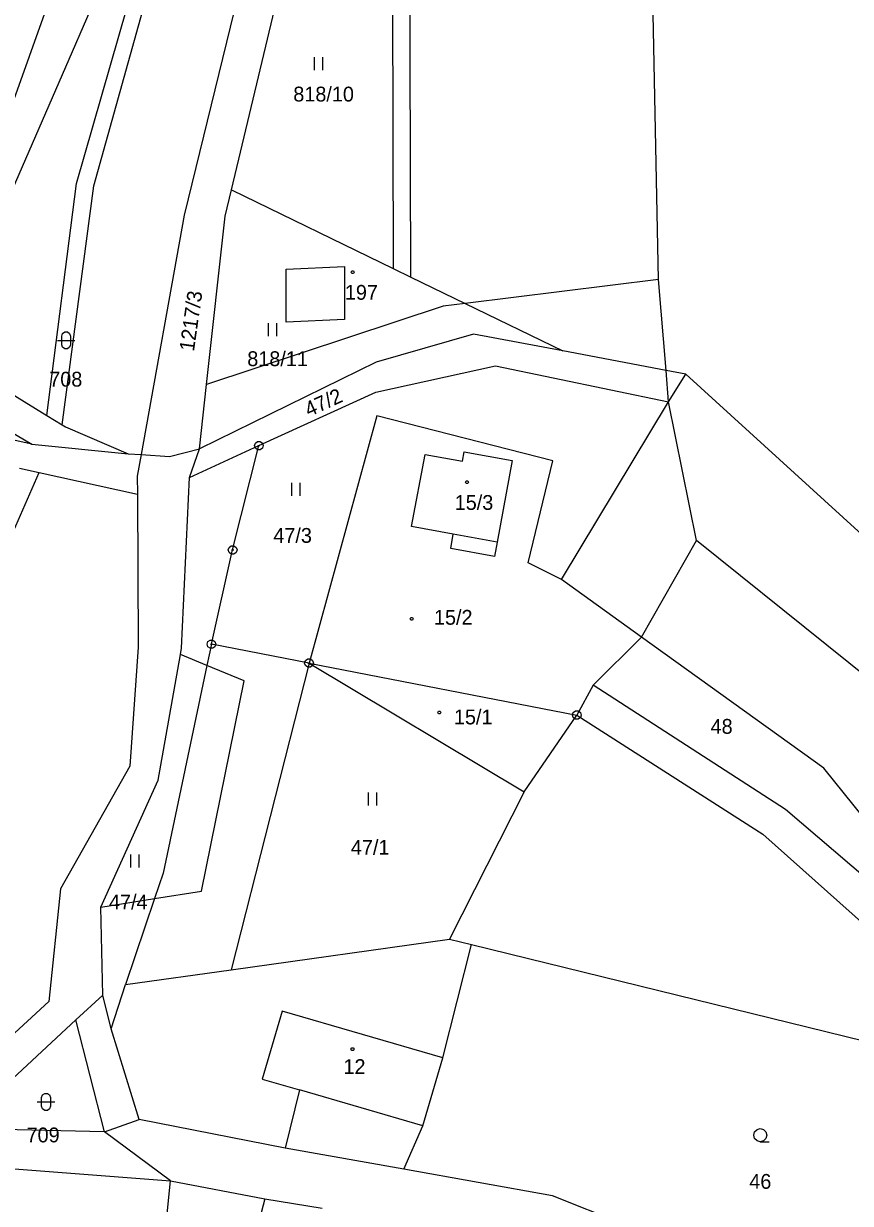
# Model space of a CAD drawing. Extents: x -694465 to -690527, y -983694 to -978978.
# Drawn here: x -691741.4 to -691646.5, y -980787.1 to -980651.8 of the extents above; entities that cross this region are included whole.
import ezdxf

# ---------------------------------------------------------------- set-up
doc = ezdxf.new("R2010")
doc.units = 0
for name, color, linetype in [('Vrstva 1', 7, 'Continuous'), ('Vrstva 18', 7, 'Continuous'), ('Vrstva 19', 7, 'Continuous'), ('Vrstva 24', 7, 'Continuous'), ('Vrstva 25', 7, 'Continuous')]:
    doc.layers.add(name, color=color, linetype=linetype)

msp = doc.modelspace()

# ---------------------------------------------------------------- linework, layer by layer
at = {"layer": 'Vrstva 1'}
for points in [[(-691668.525, -980681.164), (-691670.964, -980559.282)], [(-691736.928, -980697.827), (-691733.29, -980670.39), (-691727.725, -980650.392), (-691718.608, -980627.912), (-691709.081, -980604.134)], [(-691738.701, -980696.735), (-691735.302, -980670.152), (-691729.5, -980649.92), (-691711.265, -980604.887)], [(-691719.6, -980617.78), (-691750.73, -980689.325)], [(-691709.28, -980617.94), (-691722.95, -980673.77)], [(-691699.12, -980617.79), (-691698.96, -980679.9)], [(-691696.95, -980680.87), (-691697.12, -980616.78)], [(-691717.51, -980670.88), (-691709.24, -980636.26)], [(-691738.19, -980648.47), (-691745.62, -980669.17)], [(-691718.23, -980673.88), (-691717.51, -980670.88)], [(-691717.51, -980670.88), (-691698.96, -980679.9)], [(-691722.95, -980673.77), (-691727.877, -980701.231)], [(-691720.376, -980693.171), (-691718.23, -980673.88)], [(-691704.543, -980679.637), (-691704.543, -980685.745), (-691711.258, -980686.05), (-691711.258, -980679.942), (-691704.543, -980679.637)], [(-691698.96, -980679.9), (-691696.95, -980680.87)], [(-691696.95, -980680.87), (-691690.707, -980683.904)], [(-691668.525, -980681.164), (-691690.707, -980683.904)], [(-691667.667, -980691.573), (-691668.525, -980681.164)], [(-691690.707, -980683.904), (-691693.249, -980684.218), (-691720.376, -980693.171)], [(-691690.707, -980683.904), (-691679.52, -980689.34)], [(-691689.74, -980687.42), (-691700.91, -980690.62)], [(-691679.52, -980689.34), (-691689.74, -980687.42)], [(-691750.73, -980689.325), (-691738.701, -980696.735)], [(-691667.667, -980691.573), (-691679.52, -980689.34)], [(-691700.91, -980690.62), (-691721.2, -980700.58)], [(-691700.96, -980694.05), (-691687.23, -980691.05)], [(-691687.23, -980691.05), (-691667.37, -980695.17)], [(-691665.4, -980692), (-691667.667, -980691.573)], [(-691667.37, -980695.17), (-691667.667, -980691.573)], [(-691667.37, -980695.17), (-691665.4, -980692)], [(-691665.4, -980692), (-691620.71, -980732.71)], [(-691751.454, -980693.536), (-691740.424, -980700.027)], [(-691721.2, -980700.58), (-691720.376, -980693.171)], [(-691714.37, -980700.2), (-691700.96, -980694.05)], [(-691679.67, -980715.55), (-691667.37, -980695.17)], [(-691664.189, -980711.076), (-691667.37, -980695.17)], [(-691738.701, -980696.735), (-691736.928, -980697.827)], [(-691700.84, -980696.77), (-691708.62, -980725.14)], [(-691680.67, -980701.94), (-691700.84, -980696.77)], [(-691740.424, -980700.027), (-691744.629, -980699.131)], [(-691736.928, -980697.827), (-691736.557, -980698.055), (-691729.375, -980701.131)], [(-691740.424, -980700.027), (-691729.375, -980701.131)], [(-691722.32, -980703.84), (-691714.37, -980700.2)], [(-691717.38, -980712.16), (-691714.37, -980700.2)], [(-691729.375, -980701.131), (-691727.877, -980701.231)], [(-691727.877, -980701.231), (-691728.32, -980703.7)], [(-691727.877, -980701.231), (-691724.639, -980701.446), (-691721.2, -980700.58)], [(-691722.32, -980703.84), (-691721.2, -980700.58)], [(-691692.07, -980710.35), (-691696.86, -980709.48), (-691695.31, -980701.2), (-691691.01, -980701.98), (-691690.82, -980700.9), (-691685.33, -980701.9)], [(-691741.821, -980702.772), (-691739.583, -980703.266)], [(-691685.33, -980701.9), (-691687.04, -980711.26)], [(-691683.48, -980713.66), (-691680.67, -980701.94)], [(-691752.177, -980776.563), (-691745.117, -980741.052), (-691744.643, -980721.651), (-691743.341, -980711.832), (-691739.583, -980703.266)], [(-691739.583, -980703.266), (-691728.309, -980705.76)], [(-691728.32, -980703.7), (-691728.309, -980705.76)], [(-691723.25, -980723.43), (-691722.32, -980703.84)], [(-691728.309, -980705.76), (-691728.22, -980723.31)], [(-691687.04, -980711.26), (-691687.33, -980712.9), (-691692.37, -980711.98), (-691692.07, -980710.35)], [(-691687.04, -980711.26), (-691692.07, -980710.35)], [(-691670.47, -980722.16), (-691664.189, -980711.076)], [(-691623.724, -980758.29), (-691619.32, -980747.113), (-691664.189, -980711.076)], [(-691719.81, -980722.97), (-691717.38, -980712.16)], [(-691679.67, -980715.55), (-691683.48, -980713.66)], [(-691670.47, -980722.16), (-691679.67, -980715.55)], [(-691728.22, -980723.31), (-691729.17, -980736.97)], [(-691723.376, -980724.139), (-691723.25, -980723.43)], [(-691719.81, -980722.97), (-691720.324, -980725.403)], [(-691708.62, -980725.14), (-691719.81, -980722.97)], [(-691670.47, -980722.16), (-691676.01, -980727.68)], [(-691649.58, -980737.18), (-691670.47, -980722.16)], [(-691725.93, -980738.57), (-691723.376, -980724.139)], [(-691720.324, -980725.403), (-691723.376, -980724.139)], [(-691726.347, -980752.158), (-691720.942, -980751.296), (-691716.058, -980727.169), (-691720.324, -980725.403)], [(-691720.324, -980725.403), (-691725.36, -980749.24)], [(-691708.62, -980725.14), (-691717.552, -980760.31)], [(-691708.62, -980725.14), (-691683.95, -980739.89)], [(-691708.62, -980725.14), (-691677.9, -980731.1)], [(-691676.01, -980727.68), (-691677.9, -980731.1)], [(-691653.97, -980741.92), (-691676.01, -980727.68)], [(-691683.95, -980739.89), (-691677.9, -980731.1)], [(-691677.9, -980731.1), (-691656.57, -980744.76)], [(-691729.17, -980736.97), (-691737.11, -980751.03)], [(-691640.38, -980748.59), (-691649.58, -980737.18)], [(-691732.51, -980753.14), (-691725.93, -980738.57)], [(-691683.95, -980739.89), (-691692.52, -980756.8)], [(-691640.85, -980753.14), (-691653.97, -980741.92)], [(-691656.57, -980744.76), (-691643.14, -980756.71)], [(-691725.36, -980749.24), (-691726.347, -980752.158)], [(-691737.11, -980751.03), (-691738.45, -980763.97)], [(-691732.51, -980753.14), (-691726.347, -980752.158)], [(-691732.27, -980763.23), (-691732.51, -980753.14)], [(-691726.347, -980752.158), (-691729.68, -980762.01)], [(-691717.552, -980760.31), (-691692.52, -980756.8)], [(-691692.52, -980756.8), (-691689.985, -980757.422)], [(-691693.28, -980770.41), (-691689.985, -980757.422)], [(-691689.985, -980757.422), (-691627.85, -980772.68)], [(-691729.68, -980762.01), (-691717.552, -980760.31)], [(-691731.32, -980767.09), (-691729.68, -980762.01)], [(-691738.45, -980763.97), (-691752.177, -980776.563)], [(-691735.38, -980766.04), (-691732.27, -980763.23)], [(-691731.32, -980767.09), (-691732.27, -980763.23)], [(-691711.71, -980765.05), (-691713.99, -980772.87)], [(-691693.28, -980770.41), (-691711.71, -980765.05)], [(-691748.788, -980778.537), (-691735.38, -980766.04)], [(-691732.07, -980778.92), (-691735.38, -980766.04)], [(-691728.12, -980777.49), (-691731.32, -980767.09)], [(-691695.56, -980778.23), (-691693.28, -980770.41)], [(-691713.99, -980772.87), (-691709.72, -980774.09)], [(-691709.72, -980774.09), (-691711.35, -980780.77)], [(-691695.56, -980778.23), (-691709.72, -980774.09)], [(-691732.07, -980778.92), (-691728.12, -980777.49)], [(-691711.35, -980780.77), (-691728.12, -980777.49)], [(-691732.07, -980778.92), (-691748.788, -980778.537)], [(-691724.52, -980784.54), (-691732.07, -980778.92)], [(-691697.74, -980783.2), (-691695.56, -980778.23)], [(-691697.74, -980783.2), (-691711.35, -980780.77)], [(-691752.89, -980782.36), (-691724.52, -980784.54)], [(-691680.7, -980786.25), (-691697.74, -980783.2)], [(-691725.9, -980798.23), (-691724.52, -980784.54)], [(-691724.52, -980784.54), (-691713.68, -980786.58)], [(-691713.68, -980786.58), (-691715.96, -980795.18)], [(-691713.68, -980786.58), (-691707.12, -980787.65)], [(-691648.4, -980799.1), (-691680.7, -980786.25)]]:
    msp.add_lwpolyline(points, dxfattribs=at)
at = {"layer": 'Vrstva 24'}
for points in [[(-691714.216, -980699.724), (-691713.966, -980699.906), (-691713.87, -980700.2), (-691713.966, -980700.494), (-691714.216, -980700.676), (-691714.524, -980700.676), (-691714.774, -980700.494), (-691714.87, -980700.2), (-691714.774, -980699.906), (-691714.524, -980699.724)], [(-691717.226, -980711.684), (-691716.976, -980711.866), (-691716.88, -980712.16), (-691716.976, -980712.454), (-691717.226, -980712.636), (-691717.534, -980712.636), (-691717.784, -980712.454), (-691717.88, -980712.16), (-691717.784, -980711.866), (-691717.534, -980711.684)], [(-691719.656, -980722.494), (-691719.406, -980722.676), (-691719.31, -980722.97), (-691719.406, -980723.264), (-691719.656, -980723.446), (-691719.964, -980723.446), (-691720.214, -980723.264), (-691720.31, -980722.97), (-691720.214, -980722.676), (-691719.964, -980722.494)], [(-691708.466, -980724.664), (-691708.216, -980724.846), (-691708.12, -980725.14), (-691708.216, -980725.434), (-691708.466, -980725.616), (-691708.774, -980725.616), (-691709.024, -980725.434), (-691709.12, -980725.14), (-691709.024, -980724.846), (-691708.774, -980724.664)], [(-691677.746, -980730.624), (-691677.496, -980730.806), (-691677.4, -980731.1), (-691677.496, -980731.394), (-691677.746, -980731.576), (-691678.054, -980731.576), (-691678.304, -980731.394), (-691678.4, -980731.1), (-691678.304, -980730.806), (-691678.054, -980730.624)]]:
    msp.add_lwpolyline(points, close=True, dxfattribs=at)
for points in [[(-691714.489, -980700.2), (-691714.25, -980700.2)], [(-691717.499, -980712.16), (-691717.26, -980712.16)], [(-691719.929, -980722.97), (-691719.69, -980722.97)], [(-691708.739, -980725.14), (-691708.5, -980725.14)], [(-691678.019, -980731.1), (-691677.78, -980731.1)]]:
    msp.add_lwpolyline(points, dxfattribs=at)
at = {"layer": 'Vrstva 25'}
for points in [[(-691708.03, -980655.64), (-691708.03, -980657.14)], [(-691707.03, -980657.14), (-691707.03, -980655.64)], [(-691713.32, -980686.15), (-691713.32, -980687.65)], [(-691712.32, -980687.65), (-691712.32, -980686.15)], [(-691737.49, -980688.13), (-691735.49, -980688.13)], [(-691710.63, -980704.45), (-691710.63, -980705.95)], [(-691709.63, -980705.95), (-691709.63, -980704.45)], [(-691701.85, -980739.99), (-691701.85, -980741.49)], [(-691700.85, -980741.49), (-691700.85, -980739.99)], [(-691729.11, -980747.08), (-691729.11, -980748.58)], [(-691728.11, -980748.58), (-691728.11, -980747.08)], [(-691739.79, -980775.47), (-691737.79, -980775.47)], [(-691656.85, -980780.04), (-691657.225, -980779.939), (-691657.499, -980779.665), (-691657.6, -980779.29), (-691657.499, -980778.915), (-691657.225, -980778.641), (-691656.85, -980778.54), (-691656.475, -980778.641), (-691656.201, -980778.915), (-691656.1, -980779.29), (-691656.201, -980779.665), (-691656.475, -980779.939), (-691656.85, -980780.04), (-691655.85, -980780.041)]]:
    msp.add_lwpolyline(points, dxfattribs=at)
for points in [[(-691703.523, -980680.148), (-691703.435, -980680.3), (-691703.523, -980680.452), (-691703.697, -980680.452), (-691703.785, -980680.3), (-691703.697, -980680.148)], [(-691736.99, -980687.63), (-691736.895, -980687.336), (-691736.645, -980687.154), (-691736.335, -980687.154), (-691736.085, -980687.336), (-691735.99, -980687.63), (-691735.99, -980688.63), (-691736.085, -980688.924), (-691736.335, -980689.106), (-691736.645, -980689.106), (-691736.895, -980688.924), (-691736.99, -980688.63)], [(-691690.403, -980704.238), (-691690.315, -980704.39), (-691690.403, -980704.542), (-691690.577, -980704.542), (-691690.665, -980704.39), (-691690.577, -980704.238)], [(-691696.753, -980719.908), (-691696.665, -980720.06), (-691696.753, -980720.212), (-691696.927, -980720.212), (-691697.015, -980720.06), (-691696.927, -980719.908)], [(-691693.593, -980730.668), (-691693.505, -980730.82), (-691693.593, -980730.972), (-691693.767, -980730.972), (-691693.855, -980730.82), (-691693.767, -980730.668)], [(-691703.543, -980769.278), (-691703.455, -980769.43), (-691703.543, -980769.582), (-691703.717, -980769.582), (-691703.805, -980769.43), (-691703.717, -980769.278)], [(-691739.29, -980774.97), (-691739.195, -980774.676), (-691738.945, -980774.494), (-691738.635, -980774.494), (-691738.385, -980774.676), (-691738.29, -980774.97), (-691738.29, -980775.97), (-691738.385, -980776.264), (-691738.635, -980776.446), (-691738.945, -980776.446), (-691739.195, -980776.264), (-691739.29, -980775.97)]]:
    msp.add_lwpolyline(points, close=True, dxfattribs=at)

# ---------------------------------------------------------------- texts
at = {"layer": 'Vrstva 18'}
for s, p in [('818/10', (-691710.423, -980660.73)), ('818/11', (-691715.703, -980691.08)), ('708', (-691738.421, -980693.43)), ('47/3', (-691712.713, -980711.35)), ('48', (-691662.553, -980733.25)), ('47/1', (-691703.816, -980747.12)), ('47/4', (-691731.563, -980753.39)), ('709', (-691741.021, -980780.11)), ('46', (-691658.115, -980785.44))]:
    msp.add_text(s, height=1.7, dxfattribs=at).set_placement(p)
for s, rotation, p in [('1217/3', 81.87567, (-691721.825, -980689.461)), ('47/2', 24.29341, (-691708.641, -980696.923))]:
    msp.add_text(s, height=1.7, rotation=rotation, dxfattribs=at).set_placement(p)
at = {"layer": 'Vrstva 19'}
for s, p in [('197', (-691704.507, -980683.47)), ('15/3', (-691691.907, -980707.57)), ('15/2', (-691694.287, -980720.74)), ('15/1', (-691691.997, -980732.17)), ('12', (-691704.67, -980772.27))]:
    msp.add_text(s, height=1.7, dxfattribs=at).set_placement(p)

doc.saveas('drawing.dxf')
